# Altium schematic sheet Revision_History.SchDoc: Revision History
size A4; Author: J. Garnier; DrawnBy: J. Garnier; SheetNumber: 8; SheetTotal: 8
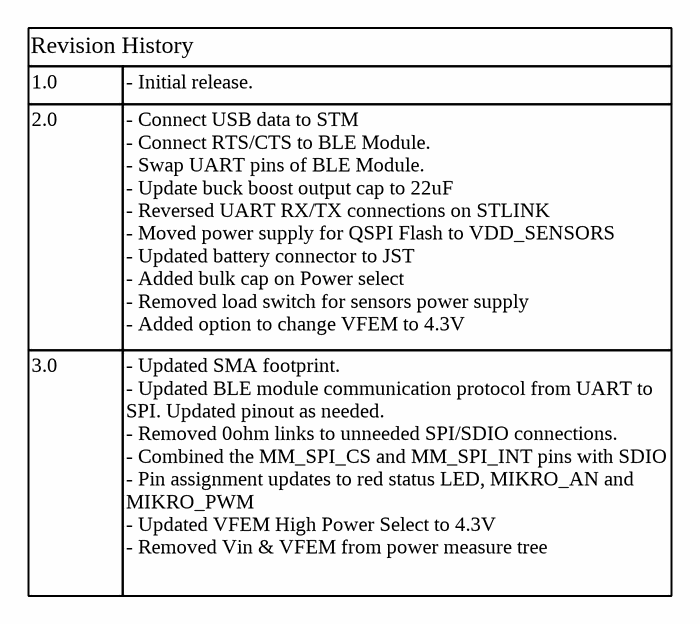
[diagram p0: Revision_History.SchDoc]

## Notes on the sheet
- Revision History
- 1.0
- - Initial release.
- 2.0
- - Connect USB data to STM
  - Connect RTS/CTS to BLE Module.
  - Swap UART pins of BLE Module.
  - Update buck boost output cap to 22uF
  - Reversed UART RX/TX connections on STLINK
  - Moved power supply for QSPI Flash to VDD_SENSORS
  - Updated battery connector to JST
  - Added bulk cap on Power select
  - Removed load switch for sensors power supply
  - Added option to change VFEM to 4.3V
- 3.0
- - Updated SMA footprint.
  - Updated BLE module communication protocol from UART to SPI. Updated pinout as needed.
  - Removed 0ohm links to unneeded SPI/SDIO connections.
  - Combined the MM_SPI_CS and MM_SPI_INT pins with SDIO
  - Pin assignment updates to red status LED, MIKRO_AN and MIKRO_PWM
  - Updated VFEM High Power Select to 4.3V
  - Removed Vin & VFEM from power measure tree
